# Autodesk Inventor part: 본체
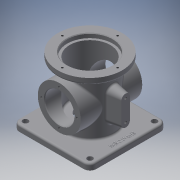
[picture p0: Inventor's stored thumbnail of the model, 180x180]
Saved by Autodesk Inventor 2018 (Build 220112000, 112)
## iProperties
Created: 2017-08
Part Number: 본체
Material: 알루미늄 6061
Document SubType Name: Modeling
Designer: mduedu
Density: 2.71 g/cm^3
Mass: 951.042 g
Surface Area: 966.503 cm^2
Volume: 350.938 cm^3
Appearance: 기본값
Author: mduedu
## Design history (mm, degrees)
sketch "스케치1"
  geometry: L1 (-62.5, -62.5)-(62.5, -62.5); L2 (62.5, -62.5)-(62.5, 62.5); L3 (62.5, 62.5)-(-62.5, 62.5); L4 (-62.5, 62.5)-(-62.5, -62.5); L5 (-62.5, -62.5)-(62.5, 62.5); L6 (62.5, -62.5)-(-62.5, 62.5); 1 further point
  constraints: 12 end point, 2 midpoint, 2 parallel, 1 horizontal, 1 perpendicular
  dimensions: "d232" = 125 distance of L3.end L2.end; "d233" = 125 distance of L2.end L1.end
extrude "돌출1" new body sketch "스케치1" distance "d5" = 10; taper "d6" = 0 deg
sketch "스케치2"
  geometry: C1 r 38 at (0, 0); 1 further point
  constraints: 1 centre point, 1 coincident
  dimensions: "d111" = 76 diameter of C1
extrude "돌출2" join sketch "스케치2" distance "d12" = 88; taper "d13" = 0 deg
sketch "스케치3"
  geometry: C1 r 52.5 at (0, 0); 1 further point
  constraints: 1 centre point, 1 coincident
  dimensions: "d114" = 105 diameter of C1
extrude "돌출3" join sketch "스케치3" distance "d19" = 10; taper "d20" = 0 deg
sketch "스케치4"
  geometry: C1 r 33 at (0, 0); 1 further point
  constraints: 1 centre point, 1 coincident
  dimensions: "d115" = 66 diameter of C1
extrude "돌출4" cut sketch "스케치4" distance "d26" = 86; taper "d27" = 0 deg
sketch "스케치5"
  geometry: C1 r 37 at (0, 0); 1 further point
  constraints: 1 centre point, 1 coincident
  dimensions: "d116" = 74 diameter of C1
extrude "돌출5" cut sketch "스케치5" distance "d29" = 7; taper "d30" = 0 deg
node "작업 평면1"
sketch "스케치18"
  geometry: L1 (-62.5, 0)-(62.5, 0) reference; C1 r 35 at (0, 54); 1 further point
  constraints: 1 centre point, 1 vertical alignment
  dimensions: "d118" = 70 diameter of C1; "d234" = 54 distance from line of C1.centre L1
extrude "돌출9" join sketch "스케치18" stored distance "d120" = 10; taper "d121" = 0 deg
hole "구멍8" diameter "d124" = 48; stored, may be unused: countersink angle "d128" = 90 deg, drill point angle "d130" = 118 deg; dims "d122" = 10, "d123" = 10, "d125" = 6, "d126" = 4, "d127" = 2, "d129" = 8
sketch "스케치9"
  geometry: C1 r 33 at (0, 0); 1 further point
  constraints: 1 centre point, 1 coincident
  dimensions: "d131" = 66 diameter of C1
extrude "돌출8" cut sketch "스케치9" distance "d43" = 16; taper "d44" = 0 deg
node "작업 평면2"
fillet "모깎기9" dims "d137" = 3
fillet "모깎기10" dims "d138" = 3
chamfer "모따기2" distance "d139" = 1; stored, may be unused: second distance "d140" = 2, angle "d141" = 45 deg
fillet "모깎기11" dims "d142" = 3
fillet "모깎기12" dims "d143" = 3
fillet "모깎기13" dims "d144" = 3
node "작업 평면3"
sketch "스케치20"
  geometry: L1 (108, -52.5)-(108, 52.5) reference; L2 (37, 7)-(71, 7); L3 (37, -7)-(71, -7); L4 (0, -33)-(0, 33) reference; A1 r 7 centre (37, 0) between (37, 7) and (37, -7); A2 r 7 centre (71, 0) between (71, 7) and (71, -7); 1 further point
  constraints: 4 end point, 4 point on circle, 3 tangent, 2 centre point, 2 horizontal alignment, 1 parallel, 1 perpendicular
  dimensions: "d203" = 14 diameter of A1; "d206" = 30 distance edge to line of A2 L1; "d207" = 48 dimension on A2 A1 (derived); "d236" = 30 distance edge to line of A1 L4
extrude "돌출10" join sketch "스케치20" stored distance "d152" = 10; taper "d153" = 10 deg
sketch "스케치21"
  geometry: C1 r 7 at (0, 71) reference; C2 r 7 at (0, 37) reference; 3 further points
  constraints: 2 coincident
hole "구멍12" sketch "스케치21" at (0, 71), (0, 37) diameter "d219" = 4.134; stored, may be unused: countersink angle "d223" = 90 deg, drill point angle "d225" = 118 deg; dims "d220" = 6, "d221" = 4, "d222" = 2, "d224" = 8
fillet "모깎기18" dims "d229" = 3
sketch "스케치23"
  geometry: C1 r 20 at (0, 0); 1 further point
  constraints: 1 centre point, 1 coincident
  dimensions: "d168" = 40 diameter of C1
extrude "돌출12" cut sketch "스케치23" extent not by distance; stored distance "d169" = 148.25; taper "d170" = 0 deg
sketch "스케치28"
  geometry: L1 (62.5, -62.5)-(62.5, 62.5) reference; 2 further points
  constraints: 1 horizontal alignment, 1 other
  dimensions: "d238" = 10 distance from line of point (52.5, 0) L1
feature "엠보싱4" sketch "스케치28" dims "d239" = 0.5, "d240" = 0
sketch "스케치25" dims "d178" = 58
  geometry: C1 r 35 at (0, 0) reference; 3 further points
  constraints: 2 vertical alignment, 1 coincident, 2 other
hole "구멍10" sketch "스케치25" at (0, 29) diameter "d179" = 3.242; stored, may be unused: countersink angle "d183" = 90 deg, drill point angle "d185" = 118 deg; dims "d180" = 4, "d181" = 4, "d182" = 2, "d184" = 6
sketch "스케치26" dims "d189" = 90
  geometry: 3 further points
  constraints: 2 vertical alignment, 1 coincident, 2 other
hole "구멍11" sketch "스케치26" at (0, 45) diameter "d190" = 3.242; stored, may be unused: countersink angle "d194" = 90 deg, drill point angle "d196" = 118 deg; dims "d191" = 4, "d192" = 4, "d193" = 2, "d195" = 6
chamfer "모따기4" distance "d200" = 1; stored, may be unused: second distance "d201" = 2, angle "d202" = 45 deg
fillet "모깎기19" dims "d241" = 10
sketch "스케치29"
  geometry: A1 r 10 centre (-52.5, 52.5) between (-52.5, 62.5) and (-62.5, 52.5) reference; A2 r 10 centre (52.5, 52.5) between (62.5, 52.5) and (52.5, 62.5) reference; A3 r 10 centre (52.5, -52.5) between (52.5, -62.5) and (62.5, -52.5) reference; A4 r 10 centre (-52.5, -52.5) between (-62.5, -52.5) and (-52.5, -62.5) reference; 5 further points
  constraints: 4 coincident
hole "구멍13" sketch "스케치29" at (-52.5, 52.5), (52.5, 52.5), (52.5, -52.5), (-52.5, -52.5) diameter "d242" = 9; stored, may be unused: countersink angle "d246" = 90 deg, drill point angle "d248" = 118 deg; dims "d243" = 6, "d244" = 4, "d245" = 2, "d247" = 8
fillet "모깎기20" dims "d249" = 3
node "솔리드1"
mirror "대칭2"
pattern_circular "원형 패턴1" dims angle "d187" = 360 deg
mirror "대칭3"
pattern_circular "원형 패턴2" dims angle "d198" = 360 deg
other parameters: "d147" = 58
